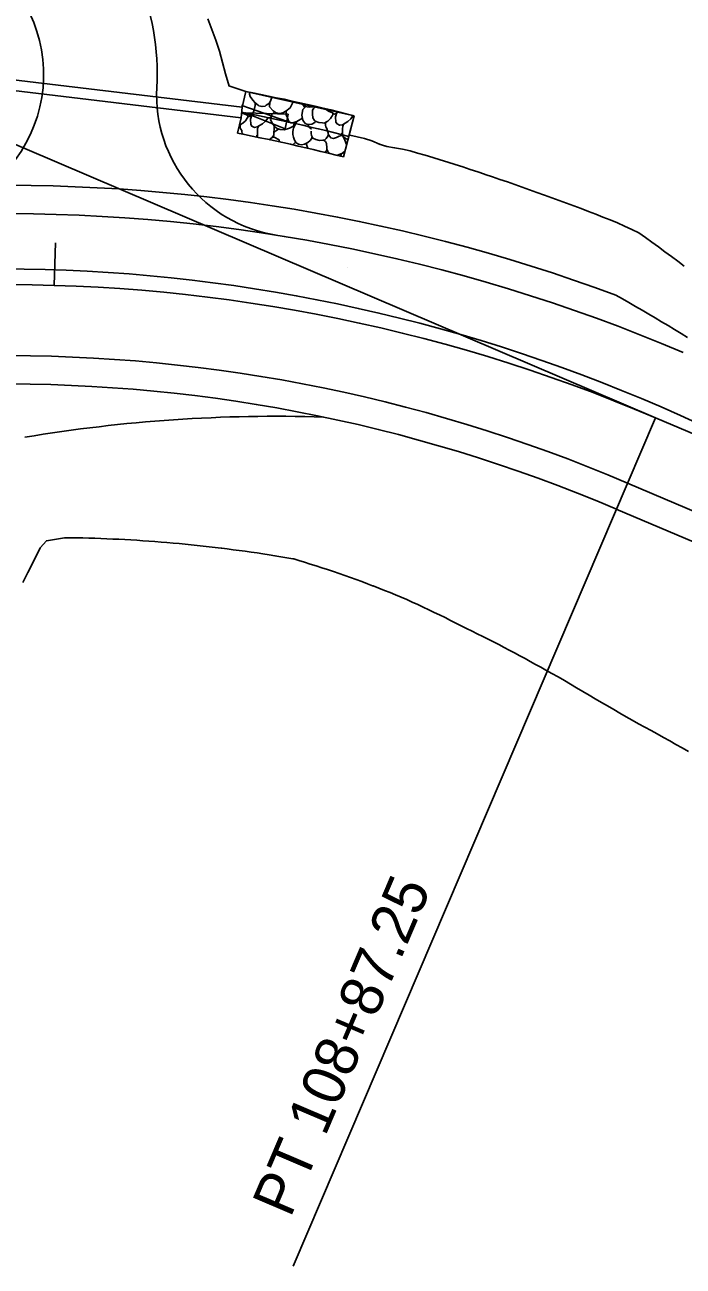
# Model space of a CAD drawing. Extents: x 834421 to 837111, y 495679 to 497078.
# Drawn here: x 835562.6 to 835655.4, y 496796.4 to 496971.3 of the extents above; entities that cross this region are included whole.
import ezdxf

# ---------------------------------------------------------------- set-up
doc = ezdxf.new("R2010")
doc.units = 0
for name, color, linetype in [('EXISTING CENTERLINE', 7, 'Continuous'), ('R_Drainage', 7, 'Continuous'), ('R_Horz Alg', 7, 'Continuous'), ('R_Horz Alg Annot', 7, 'Continuous'), ('R_Horz Alg Stationing', 7, 'Continuous'), ('R_Proposed Const Limits', 7, 'Continuous'), ('R_Proposed Road', 7, 'Continuous'), ('R_Riprap', 7, 'Continuous'), ('R_Shld', 7, 'Continuous'), ('R_Shld_GR', 7, 'Continuous'), ('R_Shoulder', 7, 'Continuous'), ('R_Special Ditch', 7, 'Continuous'), ('Transportation__x002e__STATEWIDE_HIGHWAY_LOGMILES_AHTD_point', 7, 'Continuous')]:
    doc.layers.add(name, color=color, linetype=linetype)

msp = doc.modelspace()

# ---------------------------------------------------------------- linework, layer by layer
at = {"layer": 'EXISTING CENTERLINE'}
msp.add_arc((835558.82, 496703.05), 233.86, 64.9752, 111.7879, dxfattribs=at)
at = {"layer": 'R_Drainage'}
for p, q in [((835551.52, 496964.69), (835593.22, 496959.69)), ((835551.34, 496963.21), (835593.05, 496958.2)), ((835593.22, 496959.69), (835593.05, 496958.2))]:
    msp.add_line(p, q, dxfattribs=at)
at = {"layer": 'R_Horz Alg'}
msp.add_line((835651.43, 496915.92), (835712.65, 496889.79), dxfattribs=at)
msp.add_line((835651.43, 496915.92), (835712.65, 496889.79), dxfattribs=at)
msp.add_arc((835559.63, 496700.83), 233.86, 66.8875, 115.7042, dxfattribs=at)
msp.add_arc((835559.63, 496700.83), 233.86, 66.8875, 115.7042, dxfattribs=at)
at = {"layer": 'R_Horz Alg Annot'}
for points in [[(835458.33, 496911.62), (835553.82, 496957.58), (835651.43, 496915.92)], [(835651.43, 496915.92), (835600.4, 496796.36)]]:
    msp.add_lwpolyline(points, dxfattribs=at)
at = {"layer": 'R_Horz Alg Stationing'}
msp.add_lwpolyline([(835566.89, 496940.58), (835566.71, 496934.59)], dxfattribs=at)
at = {"layer": 'R_Proposed Const Limits'}
for points in [[(835588.37, 496972.16), (835588.94, 496970.66), (835589.48, 496969.13), (835589.98, 496967.57), (835590.43, 496965.98), (835590.85, 496964.37), (835591.37, 496962.63)], [(835591.34, 496962.72), (835593.72, 496961.91), (835608.96, 496958.49), (835608.27, 496955.8)], [(835608.39, 496955.76), (835610.43, 496955.29), (835611.49, 496954.93), (835612.53, 496954.48), (835612.68, 496954.41), (835613.59, 496954.16), (835614.69, 496953.98), (835615.78, 496953.79), (835616.86, 496953.55), (835617.93, 496953.23), (835618.99, 496952.91), (835620.05, 496952.59), (835621.11, 496952.26), (835622.17, 496951.93), (835623.22, 496951.59), (835624.28, 496951.26), (835625.33, 496950.92), (835626.39, 496950.57), (835627.33, 496950.26), (835627.44, 496950.22), (835628.49, 496949.87), (835629.53, 496949.51), (835630.58, 496949.15), (835631.62, 496948.79), (835632.67, 496948.42), (835633.71, 496948.05), (835634.75, 496947.68), (835635.79, 496947.3), (835636.82, 496946.93), (835637.86, 496946.55), (835638.9, 496946.17), (835639.93, 496945.78), (835640.96, 496945.39), (835641.99, 496945), (835643.02, 496944.6), (835644.05, 496944.2), (835645.07, 496943.8), (835646.09, 496943.37), (835647.1, 496942.91), (835648.1, 496942.45), (835649.1, 496941.98), (835650.03, 496941.32), (835650.95, 496940.66), (835651.87, 496939.99), (835652.78, 496939.32), (835653.69, 496938.65), (835654.6, 496937.97), (835655.5, 496937.29)], [(835612.52, 496954.48), (835613.59, 496954.16), (835614.69, 496953.98), (835615.78, 496953.79), (835616.86, 496953.55), (835617.93, 496953.23), (835618.99, 496952.91), (835620.05, 496952.59), (835621.11, 496952.26), (835622.17, 496951.93), (835623.22, 496951.59), (835624.28, 496951.26), (835625.33, 496950.92), (835626.39, 496950.57), (835627.33, 496950.26), (835627.44, 496950.22), (835628.49, 496949.87), (835629.53, 496949.51), (835630.58, 496949.15), (835631.62, 496948.79), (835632.67, 496948.42), (835633.71, 496948.05), (835634.75, 496947.68), (835635.79, 496947.3), (835636.82, 496946.93), (835637.86, 496946.55), (835638.9, 496946.17), (835639.93, 496945.78), (835640.96, 496945.39), (835641.99, 496945), (835643.02, 496944.6), (835644.05, 496944.2), (835645.07, 496943.8), (835646.09, 496943.37), (835647.1, 496942.91), (835648.1, 496942.45), (835649.1, 496941.98), (835650.03, 496941.32), (835650.95, 496940.66), (835651.87, 496939.99), (835652.78, 496939.32), (835653.69, 496938.65), (835654.6, 496937.97), (835655.5, 496937.29)], [(835562.28, 496892.69), (835563, 496894.13), (835563.87, 496895.85), (835564.75, 496897.57), (835565.62, 496898.58), (835566.47, 496898.72), (835567.32, 496898.86), (835568.18, 496899), (835569.03, 496899.01), (835569.88, 496899), (835570.73, 496898.98), (835571.58, 496898.96), (835572.42, 496898.93), (835573.27, 496898.9), (835574.12, 496898.87), (835574.97, 496898.83), (835575.82, 496898.79), (835576.67, 496898.75), (835577.52, 496898.7), (835578.36, 496898.65), (835579.21, 496898.59), (835580.06, 496898.53), (835580.91, 496898.47), (835581.76, 496898.4), (835582.6, 496898.33), (835583.45, 496898.26), (835584.3, 496898.18), (835585.15, 496898.1), (835585.99, 496898.02), (835586.84, 496897.93), (835587.69, 496897.84), (835588.53, 496897.74), (835589.38, 496897.64), (835590.22, 496897.54), (835590.35, 496897.53), (835591.07, 496897.44), (835591.91, 496897.33), (835592.76, 496897.22), (835593.6, 496897.11), (835594.45, 496896.99), (835595.29, 496896.87), (835596.13, 496896.74), (835596.98, 496896.61), (835597.82, 496896.48), (835598.66, 496896.34), (835599.5, 496896.2), (835600.34, 496896.06), (835600.47, 496896.03), (835601.17, 496895.82), (835601.98, 496895.57), (835602.8, 496895.31), (835603.61, 496895.05), (835604.43, 496894.79), (835605.24, 496894.52), (835606.05, 496894.25), (835606.86, 496893.98), (835607.66, 496893.7), (835608.47, 496893.41), (835609.27, 496893.13), (835610.07, 496892.83), (835610.87, 496892.53), (835611.58, 496892.25), (835611.67, 496892.22), (835612.46, 496891.91), (835613.25, 496891.6), (835614.04, 496891.28), (835614.83, 496890.96), (835615.62, 496890.64), (835616.4, 496890.3), (835617.18, 496889.95), (835617.95, 496889.59), (835618.73, 496889.23), (835619.5, 496888.86), (835620.26, 496888.5), (835621.03, 496888.13), (835621.79, 496887.75), (835622.55, 496887.37), (835623.31, 496886.99), (835624.07, 496886.6), (835624.82, 496886.22), (835625.59, 496885.85), (835626.34, 496885.48), (835627.1, 496885.1), (835627.85, 496884.72), (835628.61, 496884.34), (835629.36, 496883.95), (835630.1, 496883.56), (835630.85, 496883.17), (835631.6, 496882.78), (835632.34, 496882.38), (835633.08, 496881.98), (835633.81, 496881.58), (835634.55, 496881.17), (835635.28, 496880.76), (835636.01, 496880.34), (835636.86, 496879.88), (835637.74, 496879.39), (835638.61, 496878.88), (835639.48, 496878.37), (835640.34, 496877.86), (835641.21, 496877.35), (835642.08, 496876.83), (835642.95, 496876.32), (835643.82, 496875.81), (835644.69, 496875.3), (835645.56, 496874.79), (835646.43, 496874.28), (835647.3, 496873.78), (835648.18, 496873.29), (835649.06, 496872.81), (835649.94, 496872.33), (835650.83, 496871.84), (835651.71, 496871.36), (835652.59, 496870.88), (835653.46, 496870.38), (835654.34, 496869.88), (835655.21, 496869.39), (835656.09, 496868.89)]]:
    msp.add_lwpolyline(points, dxfattribs=at)
at = {"layer": 'R_Proposed Road'}
msp.add_line((835647.5, 496906.72), (835686.82, 496889.94), dxfattribs=at)
for centre, radius, start, end in [((835545.22, 496964.3), 36, 357.0392, 99.2892), ((835545.22, 496964.3), 20, 272.9479, 99.2892), ((835601.14, 496961.41), 20, 177.0392, 260.9477), ((835559.63, 496700.83), 243.86, 66.8875, 115.7042), ((835559.63, 496700.83), 223.86, 66.8875, 115.7423)]:
    msp.add_arc(centre, radius, start, end, dxfattribs=at)
at = {"layer": 'R_Riprap'}
for p, q in [((835593.7, 496961.82), (835593.81, 496961.89)), ((835600.35, 496960.37), (835600.48, 496960.39)), ((835599.38, 496959.01), (835599.35, 496959.12)), ((835603.13, 496959.75), (835603.22, 496959.78)), ((835603.49, 496959.72), (835603.28, 496959.55)), ((835607.5, 496952.67), (835608.96, 496958.49)), ((835593.27, 496955.88), (835593.21, 496956.04)), ((835595.25, 496955.48), (835595.22, 496955.53)), ((835598.43, 496954.86), (835598.65, 496954.76))]:
    msp.add_line(p, q, dxfattribs=at)
for points in [[(835593.72, 496961.91), (835593.22, 496959.69), (835593.05, 496958.2), (835592.55, 496956.02)], [(835593.72, 496961.91), (835594.71, 496961.71), (835595.81, 496961.49), (835596.91, 496961.26), (835598.01, 496961.03), (835599.11, 496960.8), (835600.21, 496960.56), (835601.31, 496960.31), (835602.41, 496960.06), (835603.5, 496959.81), (835604.6, 496959.56), (835605.69, 496959.3), (835606.78, 496959.03), (835607.87, 496958.76), (835608.96, 496958.49)], [(835594.24, 496961.79), (835594.25, 496961.51), (835594.33, 496961.18), (835594.68, 496960.66), (835595.04, 496960.31), (835595.44, 496959.99), (835595.55, 496959.88), (835596, 496959.78), (835596.42, 496959.85), (835596.57, 496959.96), (835597.04, 496960.24), (835597.26, 496960.66), (835597.36, 496961.09)], [(835597.11, 496960.37), (835597.06, 496959.74), (835597.57, 496959.16), (835597.99, 496958.91), (835598.48, 496958.78), (835598.95, 496958.9), (835599.34, 496959.12), (835599.96, 496959.62), (835600.34, 496960.33), (835600.36, 496960.42)], [(835593.14, 496958.96), (835593.35, 496958.82), (835593.94, 496958.57), (835594.19, 496958.37), (835594.48, 496958.5), (835594.68, 496958.76), (835594.88, 496959.31), (835595.05, 496959.91), (835595.04, 496960.31)], [(835597.78, 496959.06), (835597.39, 496958.65), (835597.2, 496957.95), (835597.34, 496957.61), (835597.55, 496957.23), (835597.87, 496956.85), (835598.14, 496956.67), (835598.57, 496956.55), (835599.14, 496956.5), (835599.86, 496956.72), (835600.43, 496957.03), (835600.53, 496957.35), (835600.46, 496957.51)], [(835601.68, 496958.13), (835600.91, 496957.65), (835600.35, 496957.48), (835600.07, 496957.5), (835599.81, 496957.62), (835599.66, 496957.92), (835599.6, 496958.21), (835599.39, 496958.61), (835599.38, 496959.01)], [(835602.19, 496959.77), (835602.12, 496959.74), (835601.77, 496959.38), (835601.59, 496958.58), (835601.73, 496957.87), (835602.09, 496957.39), (835602.32, 496957.29)], [(835601.64, 496960.13), (835601.75, 496960.07), (835602.04, 496959.66)], [(835601.81, 496960.1), (835602.06, 496959.78), (835602.19, 496959.77)], [(835602.19, 496959.77), (835602.34, 496959.75), (835602.67, 496959.71), (835602.98, 496959.73), (835603.13, 496959.75)], [(835603.28, 496959.55), (835603.13, 496959.25), (835603.1, 496958.71), (835603.17, 496958.2), (835603.37, 496957.8), (835603.49, 496957.74)], [(835604.52, 496957.48), (835604.81, 496957.45), (835604.97, 496957.56), (835605.28, 496957.74), (835605.66, 496958.08), (835605.9, 496958.48), (835605.99, 496958.58), (835605.97, 496958.88)], [(835605.01, 496959.38), (835605.04, 496959.34), (835605.35, 496959.14), (835605.94, 496958.89), (835606.19, 496958.69), (835606.48, 496958.82), (835606.63, 496959.01)], [(835606.56, 496958.92), (835606.37, 496958.34), (835606.42, 496957.59), (835606.57, 496957.34), (835606.93, 496957.14), (835607.33, 496957.22), (835608.07, 496957.65), (835608.49, 496958.04), (835608.8, 496958.46), (835608.88, 496958.51)], [(835592.81, 496957.13), (835592.81, 496957.13), (835592.97, 496957.23), (835593.29, 496957.42), (835593.66, 496957.76), (835593.91, 496958.16), (835594, 496958.26), (835593.97, 496958.55)], [(835592.97, 496957.23), (835592.93, 496957.13), (835592.92, 496956.8), (835592.99, 496956.58), (835593.16, 496956.38), (835593.16, 496956.22), (835593.21, 496956.04)], [(835594.56, 496958.6), (835594.38, 496958.02), (835594.42, 496957.27), (835594.57, 496957.01), (835594.93, 496956.81), (835595.33, 496956.9), (835596.07, 496957.33), (835596.49, 496957.72), (835596.8, 496958.14), (835596.92, 496958.21), (835597.28, 496958.26)], [(835595.48, 496956.98), (835595.38, 496956.69), (835595.35, 496956.3), (835595.35, 496956.1)], [(835597.68, 496956.16), (835597.73, 496956.55), (835597.71, 496957.04)], [(835600.9, 496957.65), (835600.75, 496957.45), (835600.61, 496957.12), (835600.51, 496956.9), (835600.44, 496956.73), (835600.4, 496956.53), (835600.35, 496956.23)], [(835602.32, 496957.29), (835602.68, 496957.25), (835603.02, 496957.3), (835603.42, 496957.51), (835603.49, 496957.74)], [(835602.95, 496956.59), (835602.63, 496956.89), (835602.46, 496957.27)], [(835603.49, 496957.74), (835604.02, 496957.53), (835604.52, 496957.48)], [(835604.97, 496957.56), (835604.92, 496957.45), (835604.92, 496957.12), (835604.99, 496956.91), (835605.15, 496956.7), (835605.16, 496956.54), (835605.2, 496956.36)], [(835607.48, 496957.31), (835607.38, 496957.01), (835607.34, 496956.62), (835607.34, 496956.42)], [(835592.55, 496956.02), (835593.53, 496955.83), (835594.61, 496955.61), (835595.69, 496955.39), (835596.77, 496955.16), (835597.85, 496954.93), (835598.92, 496954.7), (835600, 496954.46), (835601.07, 496954.21), (835602.15, 496953.97), (835603.22, 496953.72), (835604.29, 496953.46), (835605.36, 496953.2), (835606.43, 496952.94), (835607.5, 496952.67)], [(835595.35, 496955.81), (835595.26, 496955.7), (835595.21, 496955.49)], [(835595.35, 496956.1), (835595.34, 496955.63), (835595.37, 496955.45)], [(835596.99, 496955.11), (835597.42, 496955.41), (835597.66, 496955.76), (835597.68, 496956.16)], [(835598.44, 496954.8), (835598.39, 496955.07), (835597.7, 496955.45), (835597.46, 496955.47)], [(835598.41, 496956.59), (835598.34, 496956.58), (835597.95, 496956.37), (835597.75, 496956.16)], [(835603.06, 496955.52), (835602.95, 496955.25), (835602.79, 496955), (835602.43, 496954.71), (835601.99, 496954.47), (835601.56, 496954.4), (835601.16, 496954.46), (835600.81, 496954.66), (835600.59, 496955.03), (835600.45, 496955.46), (835600.36, 496955.83), (835600.35, 496956.23)], [(835602.93, 496956.3), (835602.93, 496955.99), (835602.97, 496955.7), (835603.18, 496955.31), (835603.58, 496955.12), (835604.09, 496955), (835604.58, 496955.06)], [(835604.58, 496955.06), (835604.79, 496955.05), (835605.05, 496955.27), (835605.25, 496955.6), (835605.35, 496955.86)], [(835607.34, 496956.13), (835607.26, 496956.02), (835607.18, 496955.7), (835606.86, 496955.61), (835606.48, 496955.4), (835606.08, 496955.28), (835605.68, 496955.39), (835605.39, 496955.73), (835605.32, 496955.94), (835605.3, 496956.12), (835605.2, 496956.36)], [(835607.91, 496954.3), (835607.9, 496954.43), (835607.69, 496955.02), (835607.37, 496955.62), (835607.22, 496955.85)], [(835607.34, 496956.42), (835607.34, 496955.95), (835607.37, 496955.74), (835607.47, 496955.52), (835607.74, 496955.29), (835608.08, 496955.14), (835608.12, 496955.14)], [(835600.32, 496954.38), (835600.4, 496954.43), (835600.73, 496954.78)], [(835602.42, 496953.9), (835602.41, 496953.99), (835602.2, 496954.58)], [(835604.83, 496953.33), (835605.03, 496953.46), (835605.11, 496953.68), (835605.15, 496953.95), (835605.1, 496954.56), (835604.94, 496954.85), (835604.66, 496955.06)], [(835605.12, 496953.75), (835605.12, 496953.76), (835605.29, 496953.45), (835605.54, 496953.17), (835605.55, 496953.16)], [(835606.59, 496952.9), (835606.64, 496952.91), (835607.03, 496953.05), (835607.34, 496953.22), (835607.72, 496953.56)], [(835607.2, 496953.15), (835607.14, 496953.01), (835607.07, 496952.78)]]:
    msp.add_lwpolyline(points, dxfattribs=at)
at = {"layer": 'R_Shld'}
msp.add_lwpolyline([(835645.85, 496933.21), (835646.78, 496932.69), (835647.71, 496932.16), (835648.64, 496931.62), (835649.57, 496931.08), (835650.49, 496930.54), (835651.41, 496930), (835652.32, 496929.45), (835653.24, 496928.9), (835654.15, 496928.34), (835655.06, 496927.78), (835655.96, 496927.22)], dxfattribs=at)
at = {"layer": 'R_Shld_GR'}
msp.add_arc((835597.97, 496703.24), 212.89, 88.2017, 99.5738, dxfattribs=at)
at = {"layer": 'R_Shoulder'}
msp.add_line((835645.93, 496903.05), (835685.25, 496886.27), dxfattribs=at)
for radius, start, end in [(247.86, 69.6442, 115.7407), (219.86, 66.8875, 115.7426)]:
    msp.add_arc((835559.63, 496700.83), radius, start, end, dxfattribs=at)
at = {"layer": 'R_Special Ditch'}
for p, q in [((835593.6, 496958.89), (835599.25, 496956.62)), ((835599.69, 496958.7), (835593.6, 496958.89)), ((835599.25, 496956.62), (835599.69, 496958.7))]:
    msp.add_line(p, q, dxfattribs=at)
for points in [[(835593.1, 496959.94), (835593.14, 496959.92), (835594.22, 496959.55), (835595.3, 496959.18), (835596.37, 496958.8), (835597.44, 496958.42), (835598.51, 496958.04), (835599.57, 496957.65), (835599.73, 496957.59), (835600.66, 496957.39), (835601.74, 496957.14), (835602.83, 496956.89), (835603.91, 496956.64), (835604.99, 496956.38), (835606.07, 496956.12), (835607.15, 496955.85), (835608.23, 496955.58)], [(835593.14, 496958.97), (835594.12, 496958.77), (835595.21, 496958.55), (835596.3, 496958.33), (835597.39, 496958.1), (835598.48, 496957.86), (835599.57, 496957.63), (835600.66, 496957.39), (835601.74, 496957.14), (835602.83, 496956.89), (835603.91, 496956.64), (835604.99, 496956.38), (835606.07, 496956.12), (835607.15, 496955.85), (835608.23, 496955.58)], [(835608.23, 496955.58), (835607.15, 496955.85), (835606.07, 496956.12), (835604.99, 496956.38), (835603.91, 496956.64), (835602.83, 496956.89), (835601.74, 496957.14), (835600.66, 496957.39), (835599.57, 496957.63), (835598.48, 496957.86), (835597.39, 496958.1), (835596.3, 496958.33), (835595.21, 496958.55), (835594.12, 496958.77), (835593.6, 496958.88)]]:
    msp.add_lwpolyline(points, dxfattribs=at)
at = {"layer": 'Transportation__x002e__STATEWIDE_HIGHWAY_LOGMILES_AHTD_point'}
msp.add_line((835608, 496937.07), (835608, 496937.07), dxfattribs=at)

# ---------------------------------------------------------------- texts
at = {"layer": 'R_Horz Alg Annot'}
msp.add_text('PT 108+87.25', height=6, rotation=66.8875, dxfattribs=at).set_placement((835599.99, 496803.05))

doc.saveas('drawing.dxf')
